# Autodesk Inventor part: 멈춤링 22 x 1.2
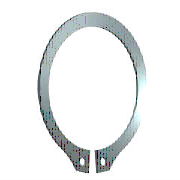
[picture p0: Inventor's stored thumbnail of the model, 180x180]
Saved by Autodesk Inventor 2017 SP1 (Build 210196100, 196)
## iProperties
IsCustomPart: 0
Created: 2021-07
Part Number: 멈춤링 22 x 1.2
Material: 강철, 연강
Description: 리테이닝 링(C형)
Document SubType Name: Modeling
Standard: KS B 1336
Designer: mdu
Standards Organization: KS
Language: ko-KR
Size Designation: 22 x 1.2
Categories: <MemberInstance><Categories><Category DisplayName="샤프트 부품" InternalName="7f7aeb1f-a693-4053-b835-cee3144e0d98" Mnemonic="SHFT"><Category DisplayName="써클립" Inter
Density: 7.86 g/cm^3
Mass: 1.82859 g
Surface Area: 5.91219 cm^2
Volume: 0.232645 cm^3
Appearance: 파란색 - 벽 페인트 - 광택
Author: mdu
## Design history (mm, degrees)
sketch "스케치1"
  geometry: L1 (-6, 0)-(6, 0) reference; L2 (0, 20.189)-(0, -80.536) reference; L3 (-48.09, 0)-(48.09, 0) reference; L4 (-0.5, -21.488)-(-0.5, -25.588); L5 (-0.5, -6.54)-(-0.5, -13.29); L6 (-2.795, 2.7)-(3.672, 2.7); L7 (0.5, -6.54)-(0.5, -13.29); L8 (0.5, -21.488)-(0.5, -25.588); C1 r 1 at (-2, -23.437); C2 r 1 at (2, -23.437); A1 r 10.5 centre (0, -11) between (0.5, -21.488) and (-0.5, -21.488); A2 r 13.025 centre (0, -10.325) between (5.149, -22.289) and (-5.149, -22.289); A3 r 14.597 centre (0, -11) between (-2.318, -25.411) and (-0.5, -25.588); A4 r 2 centre (-2, -23.437) between (-3.97, -23.781) and (-2.318, -25.411); A5 r 2 centre (-5.94, -24.126) between (-3.97, -23.781) and (-5.149, -22.289); A6 r 2 centre (5.94, -24.126) between (5.149, -22.289) and (3.97, -23.781); A7 r 2 centre (2, -23.437) between (2.318, -25.411) and (3.97, -23.781); A8 r 14.597 centre (0, -11) between (0.5, -25.588) and (2.318, -25.411)
  constraints: 16 point on circle, 12 end point, 10 centre point, 9 symmetric about line, 5 point on line, 4 tangent, 3 coincident, 2 horizontal, 1 perpendicular, 1 vertical, 5 other
  dimensions: "d0" = 21 diameter of A1 (= ND); "d1" = 4.1 distance of L4.end L4.start (= SRB2); "d6" = 0.5 distance between parallel lines of L2 L5 (= 0.25 x SD5); "d7" = 2.7 distance between parallel lines of L6 L3 (= SRB1); "d8" = 0.675 distance of A1.centre A2.centre (= 0.25 x SRB1); "d9" = 2 radius of A4 (= SD5); "d10" = 2 radius of A5 (= SD5); "d11" = 1.5 distance from line of L4 A4.centre (= 0.75 x SD5); "d12" = 2 diameter of C1 (= SD5); "d13" = 2 diameter of C2 (= SD5); "d14" = 11 distance from line of A1.centre L1 (= 0.5 x WD)
extrude "본체" new body sketch "스케치1" distance "d2" = 1.2 (= SD); taper "d3" = 0 deg
workaxis "Work Axis1"
workplane "Work Plane1"
body "Solid1"
other parameters: "WD" = 22 (= WDMIN) [user parameter; used in 1 equation term], "SD" = 1.2 [user parameter; used in 1 equation term], "SRB1" = 2.7 [user parameter; used in 2 equation terms], "ND" = 21 [user parameter; used in 1 equation term], "SRB2" = 4.1 [user parameter; used in 1 equation term], "SD5" = 2 [user parameter; used in 6 equation terms], "d15" = 0, "d16" = 0, "d17" = 0, "d41" = 0, "d42" = 0, "WDMIN" = 22 [user parameter; used in 1 equation term], "SD3" = 20.5 [user parameter], "WDMAX" = 24 [user parameter]
